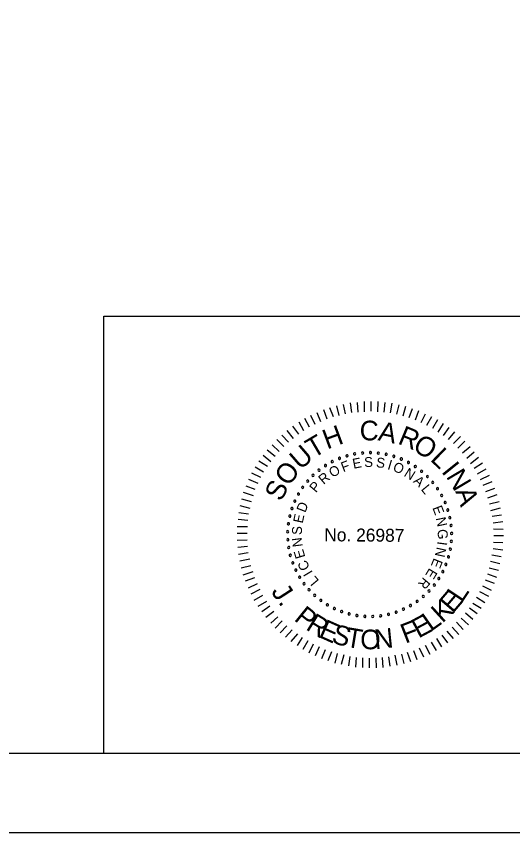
# Model space of a CAD drawing. Extents: x 96 to 240, y 601 to 689.
# Drawn here: x 184.17 to 196.67, y 601 to 621.55 of the extents above; entities that cross this region are included whole.
import ezdxf

# ---------------------------------------------------------------- set-up
doc = ezdxf.new("R2010")
doc.units = 0
for name, color, linetype in [('BR_BORDER LINES', 7, 'Continuous'), ('BR_TEXT', 7, 'Continuous'), ('Level 31', 7, 'Continuous')]:
    doc.layers.add(name, color=color, linetype=linetype)

msp = doc.modelspace()

# ---------------------------------------------------------------- linework, layer by layer
at = {"layer": 'BR_BORDER LINES'}
for p, q in [((186.375, 614.004), (207.836, 614.004)), ((186.375, 603.004), (186.375, 614.004)), ((103.173, 603.003), (237.837, 603.003))]:
    msp.add_line(p, q, dxfattribs=at)
at = {"layer": 'BR_TEXT'}
for p, q in [((192.299, 611.507), (192.246, 611.751)), ((192.464, 611.546), (192.407, 611.784)), ((192.622, 611.576), (192.586, 611.82)), ((192.78, 611.592), (192.765, 611.836)), ((192.938, 611.601), (192.94, 611.858)), ((193.106, 611.61), (193.108, 611.857)), ((193.274, 611.598), (193.283, 611.856)), ((193.435, 611.587), (193.455, 611.83)), ((193.59, 611.568), (193.633, 611.811)), ((193.751, 611.536), (193.808, 611.772)), ((193.915, 611.493), (193.979, 611.736)), ((191.841, 611.349), (191.747, 611.573)), ((191.996, 611.416), (191.912, 611.651)), ((192.154, 611.467), (192.067, 611.697)), ((194.063, 611.451), (194.15, 611.68)), ((194.22, 611.398), (194.308, 611.631)), ((194.364, 611.328), (194.475, 611.55)), ((191.413, 611.116), (191.292, 611.333)), ((191.555, 611.211), (191.433, 611.428)), ((191.693, 611.282), (191.588, 611.506)), ((194.507, 611.258), (194.633, 611.481)), ((194.658, 611.185), (194.787, 611.4)), ((191.154, 610.929), (190.995, 611.13)), ((191.289, 611.031), (191.133, 611.235)), ((194.791, 611.088), (194.927, 611.303)), ((194.924, 611.001), (195.07, 611.202)), ((191.023, 610.831), (190.856, 611.01)), ((195.054, 610.897), (195.216, 611.095)), ((195.18, 610.796), (195.353, 610.973)), ((190.788, 610.599), (190.614, 610.769)), ((190.905, 610.722), (190.728, 610.898)), ((195.292, 610.686), (195.465, 610.859)), ((195.404, 610.561), (195.595, 610.728)), ((190.687, 610.473), (190.489, 610.629)), ((195.513, 610.433), (195.7, 610.586)), ((190.496, 610.224), (190.281, 610.356)), ((190.583, 610.34), (190.385, 610.5)), ((195.608, 610.298), (195.805, 610.455)), ((195.696, 610.181), (195.907, 610.31)), ((190.399, 610.077), (190.184, 610.206)), ((195.784, 610.033), (195.998, 610.158)), ((190.259, 609.793), (190.03, 609.895)), ((190.329, 609.94), (190.103, 610.052)), ((195.855, 609.895), (196.086, 610.003)), ((190.189, 609.639), (189.957, 609.727)), ((195.926, 609.747), (196.154, 609.844)), ((190.14, 609.479), (189.894, 609.57)), ((195.994, 609.592), (196.221, 609.675)), ((196.047, 609.43), (196.278, 609.517)), ((190.091, 609.335), (189.847, 609.395)), ((196.087, 609.285), (196.328, 609.342)), ((190.062, 609.167), (189.812, 609.231)), ((196.12, 609.117), (196.361, 609.177)), ((190.001, 608.858), (189.754, 608.888)), ((190.019, 609.023), (189.776, 609.056)), ((196.153, 608.972), (196.39, 609.001)), ((189.989, 608.701), (189.732, 608.703)), ((196.179, 608.807), (196.423, 608.833)), ((189.981, 608.536), (189.73, 608.538)), ((196.185, 608.649), (196.425, 608.647)), ((196.194, 608.485), (196.438, 608.483)), ((189.986, 608.364), (189.729, 608.359)), ((196.182, 608.313), (196.422, 608.304)), ((189.996, 608.21), (189.748, 608.181)), ((190.011, 608.045), (189.767, 608.009)), ((196.174, 608.159), (196.418, 608.126)), ((190.051, 607.887), (189.8, 607.834)), ((196.11, 607.837), (196.349, 607.78)), ((196.145, 607.994), (196.382, 607.954)), ((190.077, 607.718), (189.833, 607.662)), ((196.074, 607.669), (196.314, 607.608)), ((190.124, 607.57), (189.876, 607.486)), ((196.031, 607.521), (196.261, 607.434)), ((190.171, 607.415), (189.937, 607.331)), ((190.238, 607.267), (190.007, 607.159)), ((195.905, 607.22), (196.131, 607.109)), ((195.975, 607.367), (196.201, 607.28)), ((190.306, 607.122), (190.078, 607.004)), ((195.832, 607.077), (196.061, 606.955)), ((190.373, 606.974), (190.156, 606.849)), ((190.468, 606.826), (190.251, 606.701)), ((195.759, 606.93), (195.971, 606.801)), ((190.553, 606.708), (190.353, 606.562)), ((195.578, 606.667), (195.773, 606.518)), ((195.668, 606.783), (195.877, 606.654)), ((190.655, 606.574), (190.454, 606.417)), ((190.753, 606.439), (190.577, 606.276)), ((195.37, 606.401), (195.557, 606.234)), ((195.481, 606.534), (195.665, 606.374)), ((190.869, 606.335), (190.689, 606.155)), ((190.985, 606.214), (190.815, 606.03)), ((195.256, 606.299), (195.426, 606.115)), ((191.114, 606.11), (190.952, 605.922)), ((191.248, 606.006), (191.088, 605.815)), ((195.014, 606.078), (195.173, 605.888)), ((195.142, 606.18), (195.312, 605.993)), ((191.37, 605.919), (191.245, 605.711)), ((191.51, 605.829), (191.385, 605.613)), ((194.613, 605.803), (194.739, 605.586)), ((194.748, 605.891), (194.88, 605.681)), ((194.883, 605.976), (195.025, 605.782)), ((191.647, 605.749), (191.539, 605.526)), ((191.794, 605.679), (191.696, 605.456)), ((191.948, 605.609), (191.86, 605.383)), ((194.172, 605.59), (194.256, 605.363)), ((194.317, 605.658), (194.425, 605.434)), ((194.462, 605.725), (194.583, 605.501)), ((192.105, 605.559), (192.014, 605.327)), ((192.249, 605.51), (192.192, 605.274)), ((192.414, 605.481), (192.353, 605.235)), ((192.571, 605.435), (192.532, 605.202)), ((192.729, 605.417), (192.71, 605.17)), ((192.887, 605.405), (192.885, 605.158)), ((193.055, 605.394), (193.053, 605.15)), ((193.223, 605.403), (193.228, 605.155)), ((193.384, 605.412), (193.4, 605.164)), ((193.539, 605.427), (193.578, 605.194)), ((193.701, 605.471), (193.754, 605.223)), ((193.866, 605.497), (193.926, 605.259)), ((194.014, 605.544), (194.098, 605.309))]:
    msp.add_line(p, q, dxfattribs=at)
for centre, start, end in [((192.498, 610.49), 16.1422, 196.1422), ((192.692, 610.536), 10.6038, 190.6038), ((192.692, 610.536), 190.6038, 10.6038), ((192.89, 610.563), 5.0653, 185.0653), ((192.89, 610.563), 185.0653, 5.0653), ((193.089, 610.57), 359.5268, 179.5268), ((193.089, 610.57), 179.5268, 359.5268), ((193.288, 610.558), 353.9884, 173.9884), ((193.288, 610.558), 173.9884, 353.9884), ((193.485, 610.528), 348.4499, 168.4499), ((193.485, 610.528), 168.4499, 348.4499), ((193.678, 610.478), 342.9114, 162.9114), ((192.128, 610.344), 27.2191, 207.2191), ((192.128, 610.344), 207.2191, 27.2191), ((192.31, 610.426), 21.6807, 201.6807), ((192.31, 610.426), 201.6807, 21.6807), ((192.498, 610.49), 196.1422, 16.1422), ((193.678, 610.478), 162.9114, 342.9114), ((193.865, 610.41), 157.373, 337.373), ((193.865, 610.41), 337.373, 157.373), ((194.045, 610.324), 151.8345, 331.8345), ((194.045, 610.324), 331.8345, 151.8345), ((191.793, 610.129), 38.2961, 218.2961), ((191.793, 610.129), 218.2961, 38.2961), ((191.955, 610.244), 32.7576, 212.7576), ((191.955, 610.244), 212.7576, 32.7576), ((194.216, 610.221), 146.2961, 326.2961), ((194.216, 610.221), 326.2961, 146.2961), ((194.376, 610.102), 140.7576, 320.7576), ((194.376, 610.102), 320.7576, 140.7576), ((191.642, 609.998), 43.8345, 223.8345), ((191.642, 609.998), 223.8345, 43.8345), ((194.524, 609.969), 135.2191, 315.2191), ((194.524, 609.969), 315.2191, 135.2191), ((191.382, 609.697), 54.9114, 234.9114), ((191.382, 609.697), 234.9114, 54.9114), ((191.505, 609.854), 49.373, 229.373), ((191.505, 609.854), 229.373, 49.373), ((194.658, 609.821), 129.6807, 309.6807), ((194.658, 609.821), 309.6807, 129.6807), ((194.777, 609.662), 124.1422, 304.1422), ((194.777, 609.662), 304.1422, 124.1422), ((191.275, 609.528), 60.4499, 240.4499), ((191.275, 609.528), 240.4499, 60.4499), ((194.881, 609.491), 118.6038, 298.6038), ((194.881, 609.491), 298.6038, 118.6038), ((191.185, 609.351), 65.9884, 245.9884), ((191.185, 609.351), 245.9884, 65.9884), ((194.967, 609.312), 113.0653, 293.0653), ((194.967, 609.312), 293.0653, 113.0653), ((191.113, 609.165), 71.5268, 251.5268), ((191.113, 609.165), 251.5268, 71.5268), ((195.036, 609.125), 107.5268, 287.5268), ((195.036, 609.125), 287.5268, 107.5268), ((191.058, 608.973), 77.0653, 257.0653), ((191.058, 608.973), 257.0653, 77.0653), ((195.087, 608.932), 101.9884, 281.9884), ((195.087, 608.932), 281.9884, 101.9884), ((191.023, 608.777), 82.6038, 262.6038), ((191.023, 608.777), 262.6038, 82.6038), ((195.118, 608.735), 96.4499, 276.4499), ((195.118, 608.735), 276.4499, 96.4499), ((191.006, 608.578), 88.1422, 268.1422), ((191.006, 608.578), 268.1422, 88.1422), ((195.131, 608.536), 90.9114, 270.9114), ((195.131, 608.536), 270.9114, 90.9114), ((191.009, 608.379), 93.6807, 273.6807), ((191.009, 608.379), 273.6807, 93.6807), ((195.124, 608.337), 85.373, 265.373), ((195.124, 608.337), 265.373, 85.373), ((191.031, 608.181), 99.2191, 279.2191), ((191.031, 608.181), 279.2191, 99.2191), ((195.098, 608.139), 79.8345, 259.8345), ((195.098, 608.139), 259.8345, 79.8345), ((191.072, 607.986), 104.7576, 284.7576), ((191.072, 607.986), 284.7576, 104.7576), ((195.053, 607.945), 74.2961, 254.2961), ((195.053, 607.945), 254.2961, 74.2961), ((191.132, 607.796), 110.2961, 290.2961), ((191.132, 607.796), 290.2961, 110.2961), ((191.209, 607.612), 115.8345, 295.8345), ((191.209, 607.612), 295.8345, 115.8345), ((194.989, 607.756), 68.7576, 248.7576), ((194.989, 607.756), 248.7576, 68.7576), ((191.305, 607.437), 121.373, 301.373), ((191.305, 607.437), 301.373, 121.373), ((194.809, 607.401), 57.6807, 237.6807), ((194.809, 607.401), 237.6807, 57.6807), ((194.908, 607.574), 63.2191, 243.2191), ((194.908, 607.574), 243.2191, 63.2191), ((191.416, 607.272), 126.9114, 306.9114), ((191.416, 607.272), 306.9114, 126.9114), ((194.694, 607.238), 52.1422, 232.1422), ((194.694, 607.238), 232.1422, 52.1422), ((191.543, 607.118), 132.4499, 312.4499), ((191.543, 607.118), 312.4499, 132.4499), ((194.564, 607.087), 46.6038, 226.6038), ((194.564, 607.087), 226.6038, 46.6038), ((191.684, 606.977), 137.9884, 317.9884), ((191.684, 606.977), 317.9884, 137.9884), ((191.838, 606.851), 143.5268, 323.5268), ((191.838, 606.851), 323.5268, 143.5268), ((194.263, 606.826), 35.5268, 215.5268), ((194.263, 606.826), 215.5268, 35.5268), ((194.42, 606.949), 41.0653, 221.0653), ((194.42, 606.949), 221.0653, 41.0653), ((192.004, 606.74), 149.0653, 329.0653), ((192.004, 606.74), 329.0653, 149.0653), ((192.18, 606.646), 154.6038, 334.6038), ((192.18, 606.646), 334.6038, 154.6038), ((193.918, 606.628), 24.4499, 204.4499), ((193.918, 606.628), 204.4499, 24.4499), ((194.095, 606.719), 29.9884, 209.9884), ((194.095, 606.719), 209.9884, 29.9884), ((192.363, 606.569), 160.1422, 340.1422), ((192.363, 606.569), 340.1422, 160.1422), ((192.554, 606.51), 165.6807, 345.6807), ((192.554, 606.51), 345.6807, 165.6807), ((192.749, 606.469), 351.2191, 171.2191), ((192.749, 606.469), 171.2191, 351.2191), ((192.947, 606.448), 356.7576, 176.7576), ((192.947, 606.448), 176.7576, 356.7576), ((193.146, 606.446), 2.2961, 182.2961), ((193.146, 606.446), 182.2961, 2.2961), ((193.345, 606.463), 7.8345, 187.8345), ((193.345, 606.463), 187.8345, 7.8345), ((193.541, 606.5), 13.373, 193.373), ((193.541, 606.5), 193.373, 13.373), ((193.733, 606.555), 18.9114, 198.9114), ((193.733, 606.555), 198.9114, 18.9114)]:
    msp.add_arc(centre, 0.028, start, end, dxfattribs=at)
at = {"layer": 'Level 31'}
msp.add_lwpolyline([(95.84, 601.004), (239.84, 601.004), (239.84, 689.004), (95.84, 689.004)], close=True, dxfattribs=at)

# ---------------------------------------------------------------- texts
at = {"layer": 'BR_TEXT'}
for s, height, rotation, p in [('C', 0.496, 359.5482, (192.815, 610.88)), ('A', 0.496, 348.1981, (193.261, 610.884)), ('H', 0.496, 20.3637, (191.997, 610.647)), ('R', 0.496, 337.4344, (193.754, 610.804)), ('T', 0.496, 30.4992, (191.646, 610.417)), ('O', 0.496, 326.5869, (194.123, 610.657)), ('U', 0.496, 40.8022, (191.321, 610.118)), ('L', 0.496, 315.9488, (194.573, 610.386)), ('O', 0.496, 52.0267, (191.023, 609.702)), ('F', 0.249, 20.6127, (192.402, 610.076)), ('E', 0.249, 11.4103, (192.663, 610.162)), ('S', 0.249, 2.208, (192.934, 610.206)), ('S', 0.249, 352.6608, (193.22, 610.206)), ('I', 0.249, 343.1136, (193.5, 610.157)), ('O', 0.249, 338.4392, (193.634, 610.117)), ('I', 0.496, 308.6613, (194.859, 610.089)), ('O', 0.249, 30.8477, (192.133, 609.932)), ('N', 0.249, 328.2042, (193.913, 609.991)), ('N', 0.496, 300.7037, (194.981, 609.971)), ('R', 0.249, 40.3949, (191.908, 609.756)), ('A', 0.249, 318.657, (194.149, 609.831)), ('S', 0.496, 63.2511, (190.842, 609.32)), ('P', 0.249, 49.9421, (191.716, 609.546)), ('L', 0.249, 309.4546, (194.348, 609.642)), ('A', 0.496, 289.4792, (195.218, 609.599)), ('D', 0.249, 69.0364, (191.448, 609.045)), ('E', 0.249, 291.049, (194.643, 609.181)), ('E', 0.249, 78.2388, (191.382, 608.778)), ('N', 0.249, 281.8466, (194.732, 608.921)), ('S', 0.249, 87.786, (191.359, 608.494)), ('No. 26987', 0.327, 359.5268, (191.924, 608.34)), ('G', 0.249, 272.2995, (194.779, 608.639)), ('N', 0.249, 97.3332, (191.384, 608.21)), ('I', 0.249, 262.4084, (194.778, 608.344)), ('E', 0.249, 106.5355, (191.452, 607.944)), ('N', 0.249, 257.7339, (194.759, 608.206)), ('C', 0.249, 116.4266, (191.571, 607.674)), ('E', 0.249, 248.1867, (194.687, 607.93)), ('E', 0.249, 238.9844, (194.575, 607.679)), ('I', 0.249, 121.1011, (191.644, 607.554)), ('L', 0.249, 129.9595, (191.806, 607.345)), ('R', 0.249, 229.782, (194.425, 607.449)), ('J', 0.494, 302.9559, (190.575, 607.071)), ('E', 0.494, 49.3639, (195.159, 606.504)), ('L', 0.494, 56.4247, (195.389, 606.775)), ('K', 0.494, 42.3031, (194.897, 606.263)), ('.', 0.494, 309.3974, (190.751, 606.8)), ('P', 0.494, 321.1035, (191.145, 606.363)), ('R', 0.494, 328.5359, (191.438, 606.13)), ('E', 0.494, 28.1814, (194.296, 605.887)), ('L', 0.494, 35.2422, (194.608, 606.057)), ('E', 0.494, 335.9684, (191.758, 605.938)), ('S', 0.494, 343.0292, (192.084, 605.795)), ('F', 0.494, 21.1206, (193.966, 605.758)), ('T', 0.494, 350.4617, (192.442, 605.689)), ('O', 0.494, 358.1419, (192.824, 605.629)), ('N', 0.494, 5.8221, (193.21, 605.621))]:
    msp.add_text(s, height=height, rotation=rotation, dxfattribs=at).set_placement(p)

doc.saveas('drawing.dxf')
